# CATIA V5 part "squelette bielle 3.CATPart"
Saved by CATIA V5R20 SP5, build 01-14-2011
Part number: squelette bielle 3
Bounding box of the stored display mesh (mm): x 5365.74 to 10834.35, y -10000 to 10000, z 4734.689 to 12365.631
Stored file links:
  M:\EU_thinkMotion\IAO_2010\iao\IAO_MMS_Groupe1\Problemes\gduval\Gduval\train d'aterrissage squelette + piece kinematic\squelette bielle 3.CATPart
  M:\EU_thinkMotion\IAO_2010\iao\IAO_MMS_Groupe1\Problemes\gduval\Gduval\train d'aterrissage squelette + piece kinematic\train d'aterrissage.CATProduct
  M:\EU_thinkMotion\IAO_2010\iao\IAO_MMS_Groupe1\Problemes\gduval\Gduval\train d'aterrissage squelette + piece kinematic\squelette de base.CATPart
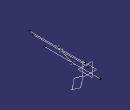
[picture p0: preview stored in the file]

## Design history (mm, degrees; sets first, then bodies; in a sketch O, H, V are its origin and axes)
Line1: type PtPt, FirstPoint Point3, SecondPoint Point2
Line2: type PtPt, FirstPoint Point1, SecondPoint Point2
Set1
  Plane1: linked copy from another document
  Point1 to Point3: linked copy from another document
Body1 (main body)
  Line3: type Normal, RefPoint Point1, RefSkin Plane1, Start -10000, End 10000
  Line4: type PtDir, RefPoint Point2, Direction Plane1, Start -10000, End 10000
  Line5: type Normal, RefPoint Point3, RefSkin Plane1, Start -10000, End 10000
  Plane2: type Offset, RefPlane Plane1, Offset 0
